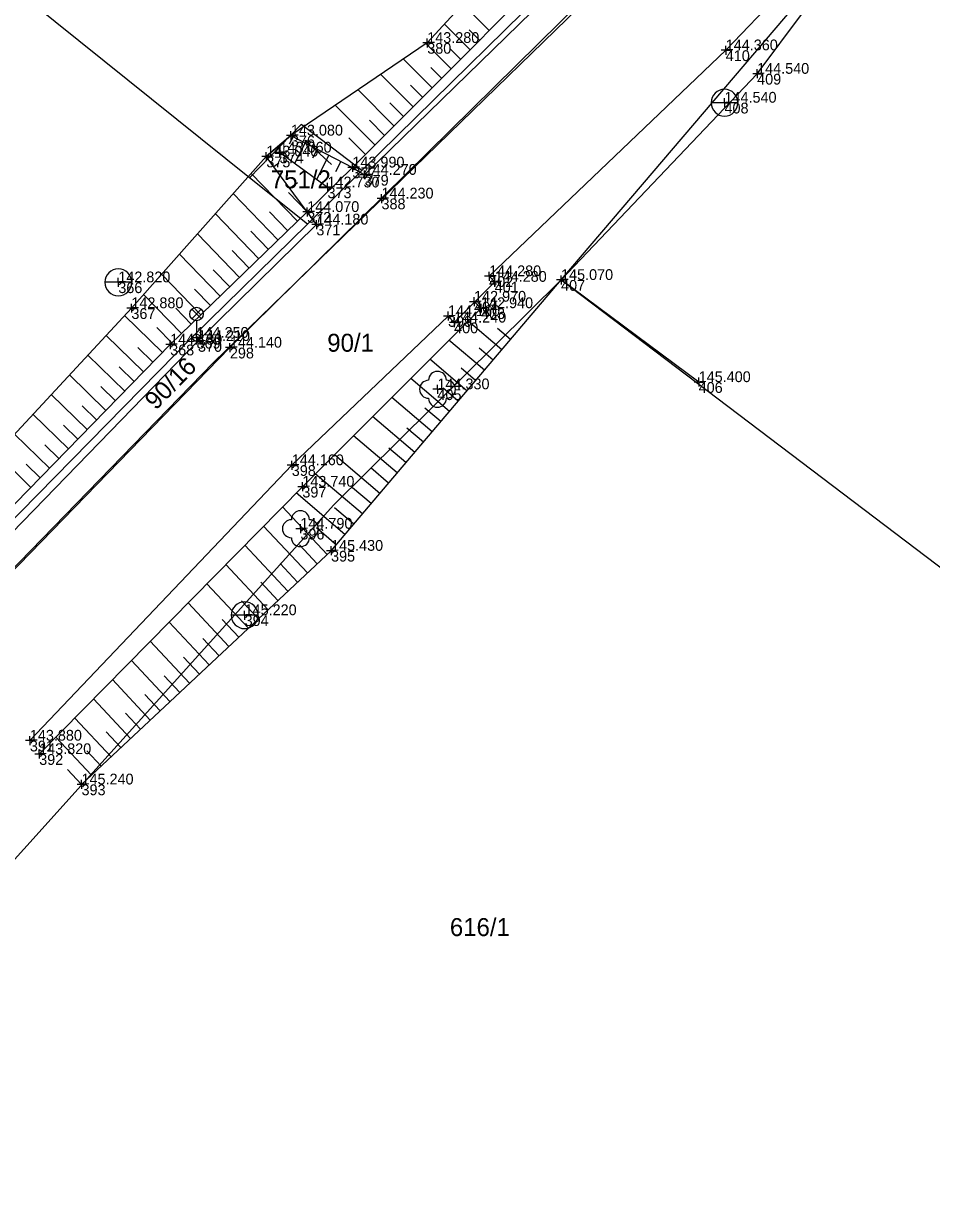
# Model space of a CAD drawing. Extents: x -748509 to -748117, y -967868 to -967533.
# Drawn here: x -748479.5 to -748428.9, y -967867.8 to -967802.6 of the extents above; entities that cross this region are included whole.
import ezdxf

# ---------------------------------------------------------------- set-up
doc = ezdxf.new("R2010")
doc.units = 0
for name, color, linetype in [('Body polohopisu', 7, 'Continuous'), ('Doplňkové značky', 7, 'Continuous'), ('KM', 7, 'Continuous'), ('Ploty_opěrné zdi', 7, 'Continuous'), ('Rozhraní ploch', 7, 'Continuous'), ('Stromy_porost', 7, 'Continuous'), ('Vstup na pozemek', 7, 'Continuous'), ('Výškopis', 7, 'Continuous'), ('Výšky bodů', 7, 'Continuous'), ('Značky IS', 7, 'Continuous'), ('Čísla bodů', 7, 'Continuous')]:
    doc.layers.add(name, color=color, linetype=linetype)

msp = doc.modelspace()

# ---------------------------------------------------------------- linework, layer by layer
at = {"layer": 'Body polohopisu'}
for p, q in [((-748457.02, -967803.73), (-748457.02, -967803.48)), ((-748457.02, -967803.73), (-748457.27, -967803.73)), ((-748457.02, -967803.73), (-748456.77, -967803.73)), ((-748457.02, -967803.73), (-748457.02, -967803.98)), ((-748440.38, -967804.14), (-748440.63, -967804.14)), ((-748440.38, -967804.14), (-748440.38, -967803.89)), ((-748440.38, -967804.14), (-748440.13, -967804.14)), ((-748440.38, -967804.14), (-748440.38, -967804.39)), ((-748438.63, -967805.45), (-748438.88, -967805.45)), ((-748438.63, -967805.45), (-748438.63, -967805.2)), ((-748438.63, -967805.45), (-748438.38, -967805.45)), ((-748438.63, -967805.45), (-748438.63, -967805.7)), ((-748440.45, -967807.06), (-748440.45, -967806.81)), ((-748440.45, -967807.06), (-748440.7, -967807.06)), ((-748440.45, -967807.06), (-748440.2, -967807.06)), ((-748440.45, -967807.06), (-748440.45, -967807.31)), ((-748464.62, -967808.89), (-748464.87, -967808.89)), ((-748464.62, -967808.89), (-748464.62, -967808.64)), ((-748464.62, -967808.89), (-748464.37, -967808.89)), ((-748464.62, -967808.89), (-748464.62, -967809.14)), ((-748465.99, -967810.06), (-748466.24, -967810.06)), ((-748465.99, -967810.06), (-748465.99, -967809.81)), ((-748465.99, -967810.06), (-748465.74, -967810.06)), ((-748465.99, -967810.06), (-748465.99, -967810.31)), ((-748465.25, -967809.84), (-748465.5, -967809.84)), ((-748465.25, -967809.84), (-748465.25, -967809.59)), ((-748465.25, -967809.84), (-748465, -967809.84)), ((-748465.25, -967809.84), (-748465.25, -967810.09)), ((-748461.19, -967810.67), (-748461.44, -967810.67)), ((-748461.19, -967810.67), (-748461.19, -967810.42)), ((-748461.19, -967810.67), (-748460.94, -967810.67)), ((-748461.19, -967810.67), (-748461.19, -967810.92)), ((-748460.51, -967811.08), (-748460.51, -967810.83)), ((-748460.51, -967811.08), (-748460.76, -967811.08)), ((-748460.51, -967811.08), (-748460.26, -967811.08)), ((-748460.51, -967811.08), (-748460.51, -967811.33)), ((-748462.58, -967811.78), (-748462.83, -967811.78)), ((-748462.58, -967811.78), (-748462.58, -967811.53)), ((-748462.58, -967811.78), (-748462.33, -967811.78)), ((-748462.58, -967811.78), (-748462.58, -967812.03)), ((-748459.57, -967812.4), (-748459.57, -967812.15)), ((-748459.57, -967812.4), (-748459.82, -967812.4)), ((-748459.57, -967812.4), (-748459.32, -967812.4)), ((-748459.57, -967812.4), (-748459.57, -967812.65)), ((-748463.71, -967813.15), (-748463.96, -967813.15)), ((-748463.71, -967813.15), (-748463.71, -967812.9)), ((-748463.71, -967813.15), (-748463.46, -967813.15)), ((-748463.71, -967813.15), (-748463.71, -967813.4)), ((-748463.2, -967813.85), (-748463.45, -967813.85)), ((-748463.2, -967813.85), (-748463.2, -967813.6)), ((-748463.2, -967813.85), (-748462.95, -967813.85)), ((-748463.2, -967813.85), (-748463.2, -967814.1)), ((-748453.57, -967816.73), (-748453.82, -967816.73)), ((-748453.57, -967816.73), (-748453.57, -967816.48)), ((-748453.57, -967816.73), (-748453.32, -967816.73)), ((-748453.57, -967816.73), (-748453.57, -967816.98)), ((-748449.56, -967816.94), (-748449.56, -967816.69)), ((-748474.24, -967817.07), (-748474.49, -967817.07)), ((-748474.24, -967817.07), (-748474.24, -967816.82)), ((-748474.24, -967817.07), (-748473.99, -967817.07)), ((-748474.24, -967817.07), (-748474.24, -967817.32)), ((-748453.26, -967817.04), (-748453.51, -967817.04)), ((-748453.26, -967817.04), (-748453.26, -967816.79)), ((-748453.26, -967817.04), (-748453.01, -967817.04)), ((-748453.26, -967817.04), (-748453.26, -967817.29)), ((-748449.56, -967816.94), (-748449.81, -967816.94)), ((-748449.56, -967816.94), (-748449.31, -967816.94)), ((-748449.56, -967816.94), (-748449.56, -967817.19)), ((-748454.41, -967818.15), (-748454.41, -967817.9)), ((-748473.51, -967818.51), (-748473.76, -967818.51)), ((-748473.51, -967818.51), (-748473.51, -967818.26)), ((-748473.51, -967818.51), (-748473.26, -967818.51)), ((-748473.51, -967818.51), (-748473.51, -967818.76)), ((-748454.41, -967818.15), (-748454.66, -967818.15)), ((-748454.41, -967818.15), (-748454.16, -967818.15)), ((-748454.41, -967818.15), (-748454.41, -967818.4)), ((-748454.02, -967818.51), (-748454.27, -967818.51)), ((-748454.02, -967818.51), (-748454.02, -967818.26)), ((-748454.02, -967818.51), (-748453.77, -967818.51)), ((-748454.02, -967818.51), (-748454.02, -967818.76)), ((-748455.86, -967818.95), (-748456.11, -967818.95)), ((-748455.86, -967818.95), (-748455.86, -967818.7)), ((-748455.86, -967818.95), (-748455.61, -967818.95)), ((-748455.86, -967818.95), (-748455.86, -967819.2)), ((-748455.52, -967819.31), (-748455.77, -967819.31)), ((-748455.52, -967819.31), (-748455.52, -967819.06)), ((-748455.52, -967819.31), (-748455.27, -967819.31)), ((-748455.52, -967819.31), (-748455.52, -967819.56)), ((-748469.88, -967820.16), (-748469.88, -967819.91)), ((-748471.35, -967820.54), (-748471.6, -967820.54)), ((-748471.35, -967820.54), (-748471.35, -967820.29)), ((-748471.35, -967820.54), (-748471.1, -967820.54)), ((-748471.35, -967820.54), (-748471.35, -967820.79)), ((-748469.88, -967820.16), (-748470.13, -967820.16)), ((-748469.8, -967820.34), (-748470.05, -967820.34)), ((-748469.88, -967820.16), (-748469.63, -967820.16)), ((-748469.88, -967820.16), (-748469.88, -967820.41)), ((-748469.8, -967820.34), (-748469.8, -967820.09)), ((-748469.8, -967820.34), (-748469.55, -967820.34)), ((-748469.8, -967820.34), (-748469.8, -967820.59)), ((-748468.02, -967820.71), (-748468.02, -967820.46)), ((-748468.02, -967820.71), (-748468.27, -967820.71)), ((-748468.02, -967820.71), (-748467.77, -967820.71)), ((-748468.02, -967820.71), (-748468.02, -967820.96)), ((-748441.89, -967822.63), (-748441.89, -967822.38)), ((-748456.45, -967823.03), (-748456.7, -967823.03)), ((-748456.45, -967823.03), (-748456.45, -967822.78)), ((-748456.45, -967823.03), (-748456.2, -967823.03)), ((-748456.45, -967823.03), (-748456.45, -967823.28)), ((-748441.89, -967822.63), (-748442.14, -967822.63)), ((-748441.89, -967822.63), (-748441.64, -967822.63)), ((-748441.89, -967822.63), (-748441.89, -967822.88)), ((-748464.57, -967827.26), (-748464.57, -967827.01)), ((-748464.57, -967827.26), (-748464.82, -967827.26)), ((-748464.57, -967827.26), (-748464.32, -967827.26)), ((-748464.57, -967827.26), (-748464.57, -967827.51)), ((-748463.98, -967828.46), (-748464.23, -967828.46)), ((-748463.98, -967828.46), (-748463.98, -967828.21)), ((-748463.98, -967828.46), (-748463.73, -967828.46)), ((-748463.98, -967828.46), (-748463.98, -967828.71)), ((-748464.09, -967830.8), (-748464.34, -967830.8)), ((-748464.09, -967830.8), (-748464.09, -967830.55)), ((-748464.09, -967830.8), (-748463.84, -967830.8)), ((-748464.09, -967830.8), (-748464.09, -967831.05)), ((-748462.38, -967832.03), (-748462.63, -967832.03)), ((-748462.38, -967832.03), (-748462.38, -967831.78)), ((-748462.38, -967832.03), (-748462.13, -967832.03)), ((-748462.38, -967832.03), (-748462.38, -967832.28)), ((-748467.2, -967835.62), (-748467.45, -967835.62)), ((-748467.2, -967835.62), (-748467.2, -967835.37)), ((-748467.2, -967835.62), (-748466.95, -967835.62)), ((-748467.2, -967835.62), (-748467.2, -967835.87)), ((-748479.17, -967842.61), (-748479.42, -967842.61)), ((-748479.17, -967842.61), (-748479.17, -967842.36)), ((-748479.17, -967842.61), (-748478.92, -967842.61)), ((-748479.17, -967842.61), (-748479.17, -967842.86)), ((-748478.65, -967843.36), (-748478.9, -967843.36)), ((-748478.65, -967843.36), (-748478.65, -967843.11)), ((-748478.65, -967843.36), (-748478.4, -967843.36)), ((-748478.65, -967843.36), (-748478.65, -967843.61)), ((-748476.29, -967845.05), (-748476.54, -967845.05)), ((-748476.29, -967845.05), (-748476.29, -967844.8)), ((-748476.29, -967845.05), (-748476.04, -967845.05)), ((-748476.29, -967845.05), (-748476.29, -967845.3))]:
    msp.add_line(p, q, dxfattribs=at)
at = {"layer": 'Doplňkové značky'}
for p, q in [((-748470.144, -967819.098), (-748469.616, -967818.57)), ((-748469.608, -967819.095), (-748470.136, -967818.566)), ((-748469.88, -967819.21), (-748469.88, -967819.96))]:
    msp.add_line(p, q, dxfattribs=at)
for centre, radius in [((-748469.88, -967818.835), 0.375), ((-748469.88, -967820.16), 0.2)]:
    msp.add_circle(centre, radius, dxfattribs=at)
at = {"layer": 'KM'}
for p, q in [((-748462.358, -967810.496), (-748463.851, -967809.15)), ((-748463.851, -967809.15), (-748463.721, -967809.495)), ((-748463.851, -967809.15), (-748463.495, -967809.245)), ((-748463.7, -967813.82), (-748460.66, -967810.84)), ((-748463.7, -967813.82), (-748466.92, -967811.24)), ((-748449.56, -967816.94), (-748425.91, -967834.85))]:
    msp.add_line(p, q, dxfattribs=at)
for points in [[(-748245.234, -967554.317), (-748248, -967560.09), (-748251.25, -967566.35), (-748259.98, -967584.86), (-748268.35, -967600.05), (-748271.49, -967604.68), (-748279.6, -967616.66), (-748283.52, -967622.09), (-748309.26, -967655.94), (-748313.11, -967660.69), (-748315.81, -967663.73), (-748339.38, -967691.21), (-748366.68, -967719.8), (-748398.22, -967751.73), (-748421.72, -967775.27), (-748446.6, -967799.82), (-748468.93, -967821.53), (-748491.86, -967845.1), (-748500.525, -967854.438)], [(-748460.66, -967810.84), (-748447.72, -967798.11), (-748423.49, -967774.11), (-748395.38, -967746.18), (-748367.64, -967717.88), (-748340.8, -967689.65), (-748338.21, -967686.92)], [(-748466.92, -967811.24), (-748500.86, -967784.02), (-748509.405, -967777.876)], [(-748449.56, -967816.94), (-748433.69, -967798.31), (-748414.8, -967779.28)], [(-748460.66, -967810.84), (-748462.3, -967809.6), (-748464.04, -967808.28), (-748466.92, -967811.24)], [(-748501.569, -967852.844), (-748493.1, -967843.53), (-748470.1, -967820.11), (-748463.7, -967813.82)], [(-748496.8, -967867.85), (-748462.22, -967829.46), (-748449.56, -967816.94)]]:
    msp.add_lwpolyline(points, dxfattribs=at)
at = {"layer": 'Ploty_opěrné zdi'}
msp.add_lwpolyline([(-748441.89, -967822.63), (-748449.56, -967816.94), (-748438.63, -967805.45)], dxfattribs=at)
at = {"layer": 'Rozhraní ploch'}
for points in [[(-748461.19, -967810.67), (-748460.51, -967811.08), (-748444.02, -967794.99), (-748439.01, -967789.86), (-748423.52, -967774.57), (-748407.07, -967758.41), (-748395.05, -967746.05), (-748380.78, -967731.92), (-748367.7, -967718.42), (-748351.79, -967701.78), (-748340.94, -967689.97), (-748337.38, -967685.41), (-748335.08, -967680.86), (-748328.55, -967672.15), (-748329.42, -967670.54)], [(-748339.41, -967690.9), (-748344.15, -967696.07), (-748355.97, -967708.43), (-748366.4, -967719.28), (-748377.52, -967730.86), (-748393.8, -967747.28), (-748406.59, -967760.01), (-748445.94, -967798.94), (-748468.02, -967820.71), (-748483.5, -967836.62)], [(-748453.57, -967816.73), (-748440.38, -967804.14), (-748434.31, -967797.8), (-748416, -967779.29), (-748414.8, -967779.28)], [(-748463.71, -967813.15), (-748461.19, -967810.67)], [(-748489.36, -967840.46), (-748469.8, -967820.34), (-748463.2, -967813.85), (-748463.71, -967813.15)], [(-748455.86, -967818.95), (-748455.52, -967819.31), (-748453.26, -967817.04), (-748453.57, -967816.73)], [(-748479.17, -967842.61), (-748464.57, -967827.26), (-748455.86, -967818.95)]]:
    msp.add_lwpolyline(points, dxfattribs=at)
at = {"layer": 'Stromy_porost'}
for centre in [(-748456.45, -967823.03), (-748464.09, -967830.8)]:
    msp.add_circle(centre, 0.0005, dxfattribs=at)
for centre, start, end in [((-748456.95, -967823.03), 89.99999, 269.99999), ((-748456.45, -967822.53), 0, 179.99999), ((-748455.95, -967823.03), 270, 89.99999), ((-748456.45, -967823.53), 179.99999, 359.99999), ((-748464.59, -967830.8), 89.99999, 269.99999), ((-748464.09, -967830.3), 0, 179.99999), ((-748463.59, -967830.8), 270, 89.99999), ((-748464.09, -967831.3), 179.99999, 359.99999)]:
    msp.add_arc(centre, 0.5, start, end, dxfattribs=at)
at = {"layer": 'Vstup na pozemek'}
msp.add_lwpolyline([(-748438.63, -967805.45), (-748436.04, -967802)], dxfattribs=at)
at = {"layer": 'Výškopis'}
for points in [[(-748490.04, -967839.69), (-748471.35, -967820.54), (-748463.71, -967813.15), (-748465.99, -967810.06), (-748465.381, -967809.54), (-748464.62, -967808.89), (-748461.19, -967810.67), (-748446.48, -967795.95), (-748440.08, -967788.81), (-748425.07, -967774.06), (-748408.42, -967758.07)], [(-748408.42, -967758.07), (-748425.87, -967772.67), (-748441.27, -967786.47), (-748448.03, -967793.95), (-748457.02, -967803.73), (-748464.62, -967808.89), (-748465.99, -967810.06)], [(-748453.572, -967803.046), (-748455.041, -967801.578)], [(-748454.632, -967804.107), (-748456.057, -967802.683)], [(-748454.102, -967803.577), (-748454.681, -967802.998)], [(-748455.692, -967805.169), (-748457.087, -967803.775)], [(-748455.162, -967804.638), (-748455.723, -967804.077)], [(-748456.753, -967806.23), (-748458.35, -967804.633)], [(-748457.813, -967807.291), (-748459.614, -967805.491)], [(-748456.222, -967805.699), (-748456.821, -967805.101)], [(-748457.283, -967806.76), (-748457.962, -967806.081)], [(-748458.873, -967808.352), (-748460.877, -967806.349)], [(-748459.933, -967809.413), (-748462.141, -967807.207)], [(-748458.343, -967807.821), (-748459.104, -967807.061)], [(-748459.403, -967808.882), (-748460.246, -967808.04)], [(-748465.381, -967809.54), (-748465.196, -967809.756)], [(-748464.495, -967808.955), (-748464.711, -967809.372)], [(-748463.829, -967809.301), (-748464.421, -967810.442)], [(-748460.464, -967809.943), (-748461.387, -967809.02)], [(-748491.7, -967838.11), (-748473.51, -967818.51), (-748465.99, -967810.06)], [(-748462.58, -967811.78), (-748465.25, -967809.84)], [(-748463.163, -967809.646), (-748463.421, -967810.143)], [(-748462.497, -967809.992), (-748463.194, -967811.334)], [(-748465.575, -967810.622), (-748465.297, -967810.417)], [(-748461.832, -967810.337), (-748462.131, -967810.914)], [(-748464.249, -967813.671), (-748466.83, -967811.004)], [(-748464.684, -967811.829), (-748464.253, -967811.511)], [(-748465.327, -967814.714), (-748467.83, -967812.127)], [(-748463.71, -967813.15), (-748464.758, -967812.067)], [(-748466.405, -967815.757), (-748468.83, -967813.251)], [(-748464.788, -967814.193), (-748465.805, -967813.142)], [(-748467.484, -967816.8), (-748469.83, -967814.375)], [(-748465.866, -967815.236), (-748466.852, -967814.217)], [(-748466.944, -967816.279), (-748467.899, -967815.292)], [(-748468.562, -967817.843), (-748470.83, -967815.498)], [(-748469.64, -967818.886), (-748471.83, -967816.622)], [(-748468.023, -967817.321), (-748468.945, -967816.367)], [(-748476.29, -967845.05), (-748462.38, -967832.03), (-748449.56, -967816.94)], [(-748470.718, -967819.929), (-748472.83, -967817.746)], [(-748469.101, -967818.364), (-748469.992, -967817.443)], [(-748478.65, -967843.36), (-748463.98, -967828.46), (-748454.02, -967818.51), (-748454.41, -967818.15)], [(-748470.179, -967819.407), (-748471.039, -967818.518)], [(-748471.784, -967820.984), (-748473.894, -967818.924)], [(-748452.864, -967820.829), (-748454.743, -967819.233)], [(-748471.257, -967820.45), (-748472.086, -967819.593)], [(-748452.379, -967820.258), (-748453.112, -967819.635)], [(-748472.831, -967822.058), (-748474.915, -967820.024)], [(-748453.835, -967821.972), (-748455.808, -967820.296)], [(-748473.879, -967823.131), (-748475.936, -967821.124)], [(-748472.307, -967821.521), (-748473.146, -967820.702)], [(-748453.35, -967821.401), (-748454.12, -967820.746)], [(-748473.355, -967822.594), (-748474.183, -967821.786)], [(-748454.807, -967823.116), (-748456.873, -967821.36)], [(-748454.321, -967822.544), (-748455.129, -967821.858)], [(-748474.927, -967824.205), (-748476.956, -967822.224)], [(-748455.778, -967824.259), (-748457.938, -967822.424)], [(-748474.403, -967823.668), (-748475.22, -967822.87)], [(-748455.292, -967823.687), (-748456.137, -967822.969)], [(-748475.974, -967825.278), (-748477.977, -967823.323)], [(-748456.749, -967825.402), (-748459.002, -967823.487)], [(-748477.022, -967826.352), (-748478.998, -967824.423)], [(-748475.45, -967824.741), (-748476.257, -967823.954)], [(-748457.72, -967826.545), (-748460.067, -967824.551)], [(-748456.263, -967824.83), (-748457.146, -967824.08)], [(-748476.498, -967825.815), (-748477.294, -967825.038)], [(-748457.235, -967825.973), (-748458.155, -967825.192)], [(-748478.07, -967827.425), (-748480.019, -967825.523)], [(-748458.691, -967827.688), (-748461.132, -967825.615)], [(-748477.546, -967826.888), (-748478.331, -967826.122)], [(-748458.206, -967827.117), (-748459.163, -967826.303)], [(-748479.117, -967828.499), (-748481.039, -967826.623)], [(-748459.662, -967828.831), (-748462.197, -967826.678)], [(-748478.594, -967827.962), (-748479.368, -967827.206)], [(-748460.634, -967829.974), (-748463.261, -967827.742)], [(-748459.177, -967828.26), (-748460.172, -967827.414)], [(-748461.605, -967831.118), (-748464.323, -967828.808)], [(-748460.148, -967829.403), (-748461.18, -967828.526)], [(-748462.601, -967832.237), (-748465.085, -967829.583)], [(-748461.119, -967830.546), (-748462.189, -967829.637)], [(-748463.696, -967833.262), (-748466.139, -967830.653)], [(-748462.09, -967831.689), (-748463.195, -967830.751)], [(-748464.791, -967834.287), (-748467.192, -967831.722)], [(-748463.149, -967832.749), (-748464.134, -967831.697)], [(-748465.886, -967835.312), (-748468.245, -967832.792)], [(-748464.244, -967833.774), (-748465.212, -967832.74)], [(-748466.982, -967836.337), (-748469.298, -967833.862)], [(-748465.339, -967834.8), (-748466.291, -967833.783)], [(-748468.077, -967837.362), (-748470.352, -967834.932)], [(-748466.434, -967835.825), (-748467.369, -967834.826)], [(-748469.172, -967838.387), (-748471.405, -967836.001)], [(-748467.529, -967836.85), (-748468.447, -967835.868)], [(-748468.624, -967837.875), (-748469.526, -967836.911)], [(-748470.267, -967839.412), (-748472.458, -967837.071)], [(-748471.362, -967840.437), (-748473.511, -967838.141)], [(-748469.719, -967838.9), (-748470.604, -967837.954)], [(-748472.457, -967841.462), (-748474.565, -967839.211)], [(-748470.814, -967839.925), (-748471.683, -967838.997)], [(-748471.91, -967840.95), (-748472.761, -967840.04)], [(-748473.552, -967842.487), (-748475.618, -967840.28)], [(-748474.647, -967843.512), (-748476.671, -967841.35)], [(-748473.005, -967841.975), (-748473.839, -967841.083)], [(-748474.1, -967843), (-748474.918, -967842.126)], [(-748475.742, -967844.537), (-748477.724, -967842.42)], [(-748475.195, -967844.025), (-748475.996, -967843.169)], [(-748476.29, -967845.05), (-748477.074, -967844.212)]]:
    msp.add_lwpolyline(points, dxfattribs=at)
at = {"layer": 'Značky IS'}
for p, q in [((-748439.703, -967807.06), (-748441.198, -967807.06)), ((-748473.493, -967817.07), (-748474.988, -967817.07)), ((-748466.453, -967835.62), (-748467.948, -967835.62))]:
    msp.add_line(p, q, dxfattribs=at)
for centre, start, end in [((-748440.45, -967807.06), 0, 180), ((-748440.45, -967807.06), 180, 0), ((-748474.24, -967817.07), 0, 180), ((-748474.24, -967817.07), 180, 0), ((-748467.2, -967835.62), 0, 180), ((-748467.2, -967835.62), 180, 0)]:
    msp.add_arc(centre, 0.747, start, end, dxfattribs=at)

# ---------------------------------------------------------------- texts
at = {"layer": 'KM'}
for s, p in [('751/2', (-748465.741, -967811.83)), ('90/1', (-748462.593, -967820.937)), ('616/1', (-748455.759, -967853.5))]:
    msp.add_text(s, height=1, dxfattribs=at).set_placement(p)
msp.add_text('90/16', height=1, rotation=45.51839, dxfattribs=at).set_placement((-748472.153, -967824.232))
at = {"layer": 'Výšky bodů'}
for s, p in [('143.280', (-748457.02, -967803.73)), ('144.360', (-748440.38, -967804.14)), ('144.540', (-748438.63, -967805.45)), ('144.540', (-748440.45, -967807.06)), ('143.080', (-748464.62, -967808.89)), ('143.040', (-748465.99, -967810.06)), ('143.060', (-748465.25, -967809.84)), ('143.990', (-748461.19, -967810.67)), ('144.270', (-748460.51, -967811.08)), ('142.730', (-748462.58, -967811.78)), ('144.230', (-748459.57, -967812.4)), ('144.070', (-748463.71, -967813.15)), ('144.180', (-748463.2, -967813.85)), ('142.820', (-748474.24, -967817.07)), ('144.280', (-748453.57, -967816.73)), ('144.280', (-748453.26, -967817.04)), ('145.070', (-748449.56, -967816.94)), ('142.880', (-748473.51, -967818.51)), ('142.970', (-748454.41, -967818.15)), ('142.940', (-748454.02, -967818.51)), ('144.160', (-748455.86, -967818.95)), ('144.240', (-748455.52, -967819.31)), ('144.180', (-748471.35, -967820.54)), ('144.250', (-748469.88, -967820.16)), ('144.210', (-748469.8, -967820.34)), ('144.140', (-748468.02, -967820.71)), ('144.330', (-748456.45, -967823.03)), ('145.400', (-748441.89, -967822.63)), ('144.160', (-748464.57, -967827.26)), ('143.740', (-748463.98, -967828.46)), ('144.790', (-748464.09, -967830.8)), ('145.430', (-748462.38, -967832.03)), ('145.220', (-748467.2, -967835.62)), ('143.880', (-748479.17, -967842.61)), ('143.820', (-748478.65, -967843.36)), ('145.240', (-748476.29, -967845.05))]:
    msp.add_text(s, height=0.6, dxfattribs=at).set_placement(p)
at = {"layer": 'Čísla bodů'}
for s, p in [('380', (-748457.02, -967804.33)), ('410', (-748440.38, -967804.74)), ('409', (-748438.63, -967806.05)), ('408', (-748440.45, -967807.66)), ('376', (-748464.62, -967809.49)), ('375', (-748465.99, -967810.66)), ('374', (-748465.25, -967810.44)), ('377', (-748461.19, -967811.27)), ('379', (-748460.51, -967811.68)), ('373', (-748462.58, -967812.38)), ('388', (-748459.57, -967813)), ('372', (-748463.71, -967813.75)), ('371', (-748463.2, -967814.45)), ('402', (-748453.57, -967817.33)), ('366', (-748474.24, -967817.67)), ('401', (-748453.26, -967817.64)), ('407', (-748449.56, -967817.54)), ('367', (-748473.51, -967819.11)), ('404', (-748454.41, -967818.75)), ('403', (-748454.02, -967819.11)), ('399', (-748455.86, -967819.55)), ('400', (-748455.52, -967819.91)), ('368', (-748471.35, -967821.14)), ('369', (-748469.88, -967820.76)), ('370', (-748469.8, -967820.94)), ('298', (-748468.02, -967821.31)), ('405', (-748456.45, -967823.63)), ('406', (-748441.89, -967823.23)), ('398', (-748464.57, -967827.86)), ('397', (-748463.98, -967829.06)), ('396', (-748464.09, -967831.4)), ('395', (-748462.38, -967832.63)), ('394', (-748467.2, -967836.22)), ('391', (-748479.17, -967843.21)), ('392', (-748478.65, -967843.96)), ('393', (-748476.29, -967845.65))]:
    msp.add_text(s, height=0.6, dxfattribs=at).set_placement(p)

doc.saveas('drawing.dxf')
